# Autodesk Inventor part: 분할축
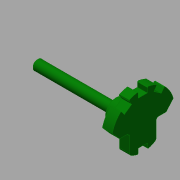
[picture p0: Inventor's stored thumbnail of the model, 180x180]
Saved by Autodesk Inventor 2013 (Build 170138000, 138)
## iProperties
Created: 2016-11
Part Number: 분할축
Material: 강철, 연강
Document SubType Name: Modeling
Designer: mduedu
Density: 1 g/cm^3
Author: mduedu
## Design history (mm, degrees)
sketch "스케치1"
  geometry: C1 r 38 at (0, 0); 1 further point
  constraints: 1 centre point, 1 coincident
  dimensions: "d0" = 76 diameter of C1
extrude "돌출1" new body sketch "스케치1" distance "d1" = 12; taper "d2" = 0 deg
sketch "스케치2"
  geometry: L1 (0, 38)-(0, -38); L2 (5.5, 37.6)-(5.5, 31); L3 (5.5, 31)-(-5.5, 31); L4 (-5.5, 31)-(-5.5, 37.6); A1 r 38 centre (0, 0) between (0, 38) and (0, -38) reference; A2 r 38 centre (0, 0) between (5.5, 37.6) and (-5.5, 37.6); 2 further points
  constraints: 8 end point, 6 point on circle, 2 coincident, 2 vertical, 1 centre point, 1 horizontal, 1 midpoint, 1 parallel, 1 symmetric about line
  dimensions: "d3" = 11 distance of L2.end L3.end; "d5" = 31 distance from line of L3 point (0, 0)
extrude "돌출2" cut sketch "스케치2" stored distance "d7" = 12; taper "d8" = 0 deg
sketch "스케치3"
  geometry: L1 (-16, 0)-(-38, 0); L2 (16, 0)-(38, 0); L3 (0, -28)-(0, 28); L4 (-16, -22.978)-(-16, 0); L5 (16, -22.978)-(16, 0); A1 r 38 centre (0, 0) between (-5.5, 37.6) and (-17.061, 33.955) reference; A2 r 38 centre (0, 0) between (-38, 0) and (38, 0); A3 r 28 centre (0, 0) between (-16, -22.978) and (16, -22.978); 4 further points
  constraints: 10 end point, 7 point on circle, 3 coincident, 2 centre point, 2 horizontal alignment, 2 midpoint, 2 parallel, 1 collinear, 1 horizontal, 1 perpendicular, 1 other
  dimensions: "d13" = 32 distance between parallel lines of L5 L4; "d14" = 28 radius of A3
extrude "돌출3" cut sketch "스케치3" stored distance "d15" = 12; taper "d16" = 0 deg
sketch "스케치4"
  geometry: L1 (0, 0)-(0, -28); L2 (5.5, -27.455)-(5.5, -21); L3 (5.5, -21)-(-5.5, -21); L4 (-5.5, -21)-(-5.5, -27.455); A1 r 28 centre (0, 0) between (-16, -22.978) and (16, -22.978) reference; A2 r 28 centre (0, 0) between (16, -22.978) and (0, -28); A3 r 28 centre (0, 0) between (-5.5, -27.455) and (5.5, -27.455); 1 further point
  constraints: 8 end point, 7 point on circle, 2 centre point, 2 coincident, 1 horizontal, 1 parallel, 1 other
  dimensions: "d17" = 11 distance between parallel lines of L2 L4; "d19" = 21 distance from line of L3 point (0, 0)
extrude "돌출4" cut sketch "스케치4" stored distance "d20" = 12; taper "d21" = 0 deg
sketch "스케치5"
  geometry: C1 r 13 at (0, 0); 1 further point
  constraints: 1 centre point, 1 coincident
  dimensions: "d22" = 26 diameter of C1
extrude "돌출5" join sketch "스케치5" distance "d23" = 20; taper "d24" = 0 deg
sketch "스케치6"
  geometry: C1 r 6 at (0, 0); 1 further point
  constraints: 1 centre point, 1 coincident
  dimensions: "d25" = 12 diameter of C1
extrude "돌출6" join sketch "스케치6" distance "d26" = 95; taper "d27" = 0 deg
fillet "모깎기1" dims "d28" = 3
chamfer "모따기1" distance "d29" = 1; stored, may be unused: second distance "d30" = 2, angle "d31" = 45 deg
sketch "스케치7"
  geometry: L1 (-20, 13)-(-20, -13) reference; L2 (-20, 6)-(-114, 6) reference; L3 (0, 0)-(-20, 0); C1 r 1 at (-21, 6)
  constraints: 2 end point, 1 centre point, 1 midpoint, 1 tangent
  dimensions: "d32" = 2 diameter of C1; "d33" = 10 dimension on C1 L3
revolve "회전1" sketch "스케치7" stored, may be unused: angle "d34" = 90 deg
chamfer "모따기2" distance "d35" = 1; stored, may be unused: second distance "d36" = 2, angle "d37" = 45 deg
chamfer "모따기3" distance "d38" = 10; stored, may be unused: second distance "d39" = 2, angle "d40" = 45 deg
chamfer "모따기4" distance "d41" = 1; stored, may be unused: second distance "d42" = 2, angle "d43" = 45 deg
fillet "모깎기2" dims "d44" = 3
node "솔리드1"
pattern_circular "원형 패턴1" dims angle "d10" = 35 deg
other parameters: "d12" = 56
